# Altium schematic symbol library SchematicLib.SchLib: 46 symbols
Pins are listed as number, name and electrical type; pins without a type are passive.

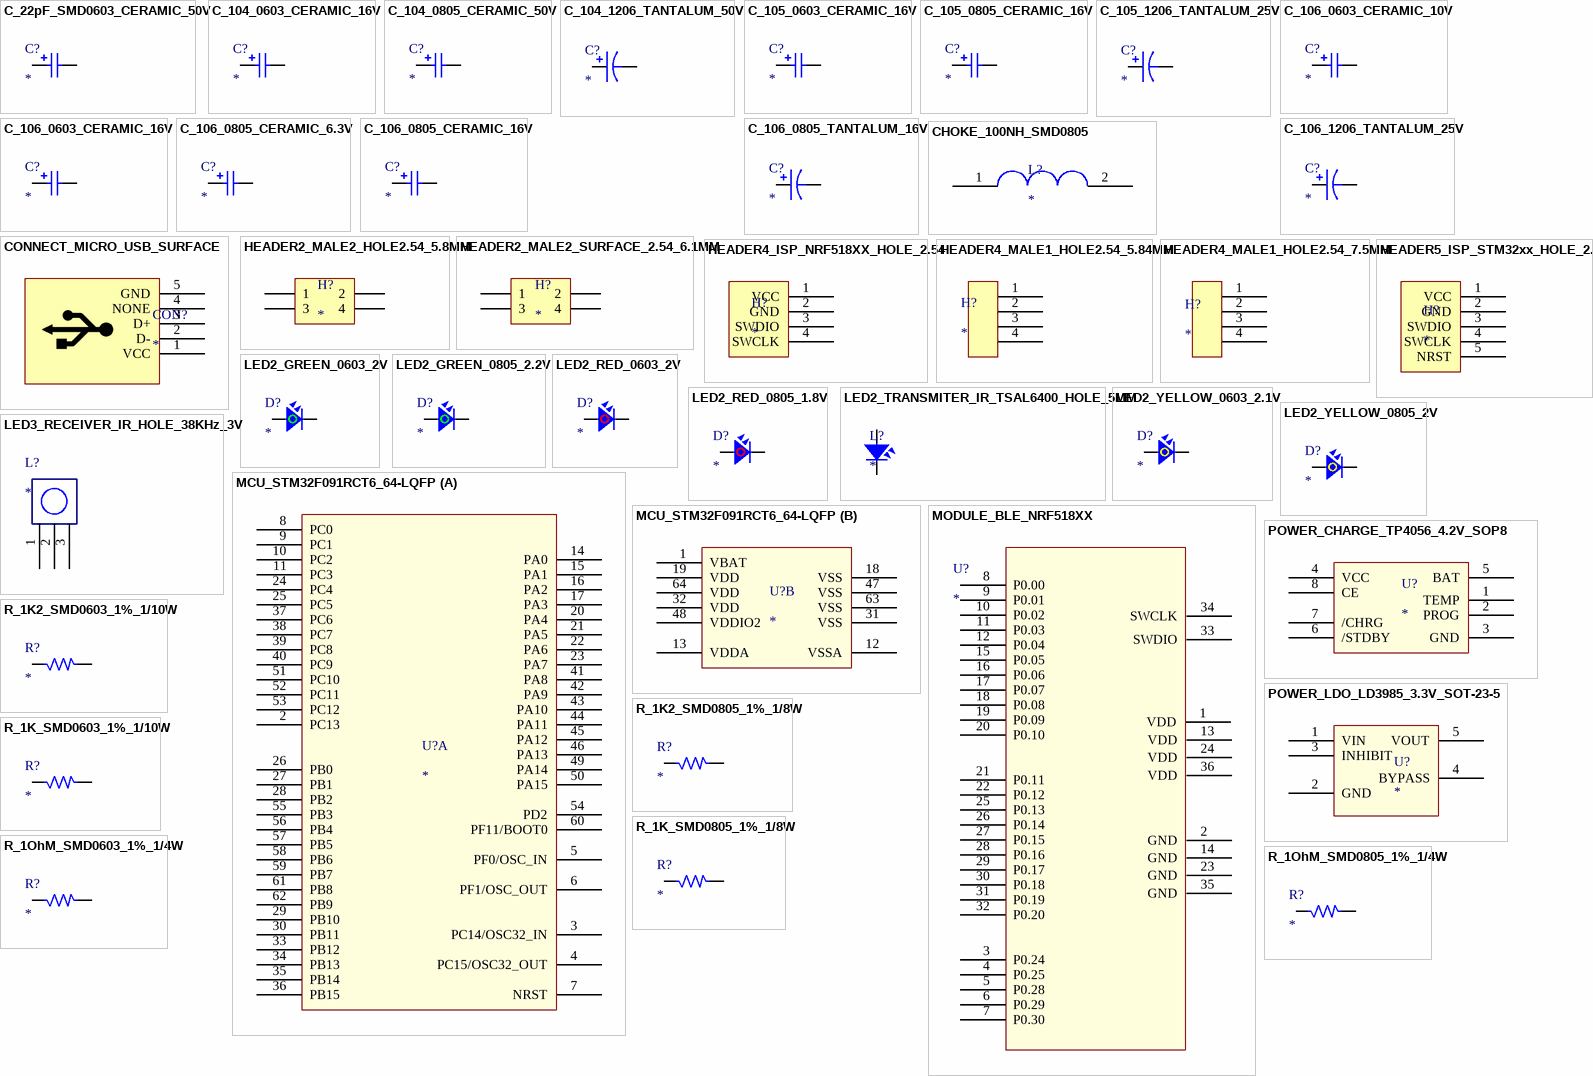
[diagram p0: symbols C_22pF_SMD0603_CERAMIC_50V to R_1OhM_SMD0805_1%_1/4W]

## C_22pF_SMD0603_CERAMIC_50V
designator C?
CAP CER 22PF 50V NP0 0603; Manufacturer: Murata Electronics North America; Manufacturer Part Number: GQM1885C1H220JB01D; Tolerance: ±5%; Temperature Coefficient: C0G, NP0
footprint CAP_SMD0603 (Compoment SMD 60x30mil)
pins: 1, 2

## C_104_0603_CERAMIC_16V
designator C?
CAP CER 0.1UF 16V X7R 0603; Manufacturer: Murata Electronics North America; Manufacturer Part Number: GRM188R71C104KA01D; Capacitance: 0.10µF; Tolerance: ±10%
footprint CAP_SMD0603 (Compoment SMD 60x30mil)
pins: 1, 2

## C_104_0805_CERAMIC_50V
designator C?
CAP CER 0.1UF 50V X7R 0805; Manufacturer: AVX Corporation; Manufacturer Part Number: 08055C104KAT2A; Capacitance: 0.10µF; Tolerance: ±10%
footprint CAP_SMD0805 (Compoment SMD 80x50mil)
pins: 1, 2

## C_104_1206_TANTALUM_50V
designator C?
CAP TANT 0.1UF 50V 10% 1206; Manufacturer: Kemet; Manufacturer Part Number: T491A104K050AT; Manufacturer Size Code: A; Capacitance: 0.1µF; ESR (Equivalent Series Resistance): 20 Ohm; Type: Molded; Lifetime @ Temp.: 2000 Hrs @ 85°C
footprint CAP_SMD1206_TANTALUM (Compoment SMD 80x50mil)
pins: 1, 2

## C_105_0603_CERAMIC_16V
designator C?
CAP CER 1UF 16V X5R 0603; Manufacturer: Murata Electronics North America; Manufacturer Part Number: GRM188R61C105KA93D; Capacitance: 1µF; Tolerance: ±10%
footprint CAP_SMD0603 (Compoment SMD 60x30mil)
pins: 1, 2

## C_105_0805_CERAMIC_16V
designator C?
CAP CER 1UF 16V X7R 0805; Manufacturer: Murata Electronics North America; Manufacturer Part Number: GRM21BR71C105KA01L; Capacitance: 1µF; Tolerance: ±10%
footprint CAP_SMD0805 (Compoment SMD 80x50mil)
pins: 1, 2

## C_105_1206_TANTALUM_25V
designator C?
CAP TANT 1UF 25V 10% 1206; Manufacturer: Kemet; Manufacturer Part Number: T491A105K025AT; Manufacturer Size Code: A; Capacitance: 1µF; ESR (Equivalent Series Resistance): 8 Ohm; Type: Molded; Lifetime @ Temp.: 2000 Hrs @ 85°C
footprint CAP_SMD1206_TANTALUM (Compoment SMD 80x50mil)
pins: 1, 2

## C_106_0603_CERAMIC_10V
designator C?
CAP CER 10UF 10V X5R 0603; Manufacturer: Murata Electronics North America; Manufacturer Part Number: GRM188R61A106KE69D; Capacitance: 10µF; Tolerance: ±10%
footprint CAP_SMD0603 (Compoment SMD 60x30mil)
pins: 1, 2

## C_106_0603_CERAMIC_16V
designator C?
CAP CER 10UF 16V X5R 0603; Manufacturer: Murata Electronics North America; Manufacturer Part Number: GRM188R61C106KAALD; Capacitance: 10µF; Tolerance: ±10%
footprint CAP_SMD0603 (Compoment SMD 60x30mil)
pins: 1, 2

## C_106_0805_CERAMIC_6.3V
designator C?
CAP CER 10UF 6.3V X5R 0805; Manufacturer: Murata Electronics North America; Manufacturer Part Number: GRM219R60J106KE19D; Capacitance: 10µF; Tolerance: ±10%
footprint CAP_SMD0805 (Compoment SMD 80x50mil)
pins: 1, 2

## C_106_0805_CERAMIC_16V
designator C?
CAP CER 10UF 16V X5R 0805; Manufacturer: Murata Electronics North America; Manufacturer Part Number: GRM21BR61C106KE15K; Capacitance: 10µF; Tolerance: ±10%
footprint CAP_SMD0805 (Compoment SMD 80x50mil)
pins: 1, 2

## C_106_0805_TANTALUM_16V
designator C?
CAP TANT 10UF 16V 10% 0805; Manufacturer: AVX Corporation; Manufacturer Part Number: TPCR106K016R1800; Manufacturer Size Code: R; Capacitance: 10µF; ESR (Equivalent Series Resistance): 1.8 Ohm; Type: Molded
footprint CAP_SMD0805 - TANTALUM (Compoment SMD 80x50mil)
pins: 1, 2

## C_106_1206_TANTALUM_25V
designator C?
CAP TANT 10UF 25V 10% 1206; Manufacturer: AVX Corporation; Manufacturer Part Number: F951E106KAAAQ2; Manufacturer Size Code: A; Capacitance: 10µF; ESR (Equivalent Series Resistance): 2 Ohm; Type: Conformal Coated
footprint CAP_SMD1206_TANTALUM (Compoment SMD 80x50mil)
pins: 1, 2

## CHOKE_100NH_SMD0805
designator L?
FIXED IND 100NH 300MA 900 MOHM; Manufacturer: Jaro Components Inc.; Manufacturer Part Number: HFI-201209-R10J; Type: Wirewound; Material - Core: Ceramic; Tolerance: ±5%; Shielding: Unshielded; DC Resistance (DCR): 900 mOhm Max; Q @ Freq: 18 @ 100MHz; Frequency - Self Resonant: 600MHz; Frequency - Test: 100MHz
pins: 1, 2

## CONNECT_MICRO_USB_SURFACE
designator CON?
CONN RCPT STD MICRO USB TYPE B; Manufacturer: Amphenol FCI; Manufacturer Part Number: 10103593-0001LF; Connector Type: USB - micro B; Number of Contacts: 5; Gender: Receptacle; Specifications: USB 2.0; Regulator Topology: Positive Fixed; Voltage - Output: 3.3V; Current - Output: 150mA; Voltage - Dropout (Typical): 0.06V @ 150mA; Number of Regulators: 1; Voltage - Input: Up to 6V; Current - Limit (Min): 300mA
footprint CON_MICRO_USB_HOLE
footprint Micro_USB
pins: 1 VCC, 2 D-, 3 D+, 4 NONE, 5 GND

## HEADER2_MALE2_HOLE2.54_5.8MM
designator H?
02+02 DIL VERT PIN HDR; Manufacturer: Harwin Inc.; Manufacturer Part Number: M20-9760246; Connector Type: Header, Unshrouded, Breakaway; Number of Positions: 4; Number of Positions Loaded: All; Pitch: 0.100" (2.54mm)
footprint HEADER2_MALE2_HOLE2.54 (HEADER, SINGLE, DISTANCE = 100mil)
pins: 1, 2, 3, 4

## HEADER2_MALE2_SURFACE_2.54_6.1MM
designator H?
CONN HEADER 4POS TIN SMD; Manufacturer: Molex, LLC; Manufacturer Part Number: 0015912040; Connector Type: Header, Unshrouded, Breakaway; Number of Positions: 4; Number of Positions Loaded: All; Pitch: 0.100" (2.54mm)
footprint HEADER2_MALE2_SURFACE2.54 (HEADER, SINGLE, DISTANCE = 100mil)
pins: 1, 2, 3, 4

## HEADER4_ISP_NRF518XX_HOLE_2.54
designator H?
CONN HEADER 4POS .100 STR TIN; Manufacturer: Amphenol FCI; Manufacturer Part Number: 68002-404HLF; Connector Type: Header, Unshrouded; Number of Positions: 4; Number of Positions Loaded: All; Pitch: 0.100" (2.54mm)
footprint HEADER4_ISP_NRF518xx_SUR1.27 (HEADER, SINGLE, DISTANCE = 100mil)
pins: 1 VCC, 2 GND, 3 SWDIO, 4 SWCLK

## HEADER4_MALE1_HOLE2.54_5.84MM
designator H?
CONN HEADER 4POS .100 STR TIN; Manufacturer: Amphenol FCI; Manufacturer Part Number: 68002-404HLF; Connector Type: Header, Unshrouded; Number of Positions: 4; Number of Positions Loaded: All; Pitch: 0.100" (2.54mm)
pins: 1, 2, 3, 4

## HEADER4_MALE1_HOLE2.54_7.5MM
designator H?
CONN HEADER VERT 4POS .100 TIN; Manufacturer: TE Connectivity AMP Connectors; Manufacturer Part Number: 640456-4; Connector Type: Header, Unshrouded; Number of Positions: 4; Number of Positions Loaded: All; Pitch: 0.100" (2.54mm)
pins: 1, 2, 3, 4

## HEADER5_ISP_STM32xx_HOLE_2.54
designator H?
CONN HEADER 5 POS 2.54; Manufacturer: Wurth Electronics Inc; Manufacturer Part Number: 61300511121; Connector Type: Header, Unshrouded; Number of Positions: 5; Number of Positions Loaded: All; Pitch: 0.100" (2.54mm)
footprint HEADER5_ISP_STM32F0xx_SUR1.27 - duplicate (HEADER, SINGLE, DISTANCE = 100mil)
pins: 1 VCC, 2 GND, 3 SWDIO, 4 SWCLK, 5 NRST

## LED2_GREEN_0603_2V
designator D?
LED GREEN CLEAR 0603 SMD; Manufacturer: Lite-On Inc.; Manufacturer Part Number: LTST-C191KGKT; Lens Color: Colorless; Millicandela Rating: 35mcd; Lens Style/Size: Rectangle with Flat Top, 1.10mm x 0.80mm; Voltage - Forward (Vf) (Typ): 2V; Current - Test: 20mA; Viewing Angle: 130°; Wavelength - Dominant: 571nm; Wavelength - Peak: 574nm
footprint LED_GREEN_SMD0603 (Compoment SMD 60x30mil)
pins: 1, 2

## LED2_GREEN_0805_2.2V
designator D?
LED GREEN DIFFUSED 0805 SMD; Manufacturer: OSRAM Opto Semiconductors Inc.; Manufacturer Part Number: LG R971-KN-1; Lens Color: White; Millicandela Rating: 26.05mcd; Lens Style/Size: Rectangle with Flat Top, 1.30mm x 1.25mm; Voltage - Forward (Vf) (Typ): 2.2V; Current - Test: 20mA; Viewing Angle: 160°; Wavelength - Dominant: 570nm; Wavelength - Peak: 572nm
footprint LED_GREEN_SMD0805 (Compoment SMD 80x50mil)
pins: 1, 2

## LED2_RED_0603_2V
designator D?
LED RED CLEAR 0603 SMD; Manufacturer: Lite-On Inc.; Manufacturer Part Number: LTST-C191KRKT; Lens Color: Colorless; Millicandela Rating: 54mcd; Lens Style/Size: Rectangle with Flat Top, 1.10mm x 0.80mm; Voltage - Forward (Vf) (Typ): 2V; Current - Test: 20mA; Viewing Angle: 130°; Wavelength - Dominant: 631nm; Wavelength - Peak: 639nm
footprint LED_RED_SMD0603 (Compoment SMD 60x30mil)
pins: 1, 2

## LED2_RED_0805_1.8V
designator D?
LED RED DIFFUSED 0805 SMD; Manufacturer: OSRAM Opto Semiconductors Inc.; Manufacturer Part Number: LH R974-LP-1; Lens Color: White; Millicandela Rating: 41mcd; Lens Style/Size: Rectangle with Flat Top, 1.30mm x 1.25mm; Voltage - Forward (Vf) (Typ): 1.8V; Current - Test: 20mA; Viewing Angle: 160°; Wavelength - Dominant: 645nm; Wavelength - Peak: 660nm
footprint LED_RED_SMD0805 (Compoment SMD 80x50mil)
pins: 1, 2

## LED2_TRANSMITER_IR_TSAL6400_HOLE_5MM
designator L?
EMITTER IR 940NM 100MA RADIAL; Manufacturer: Vishay Semiconductor Opto Division; Manufacturer Part Number: TSAL6400; Type: Infrared (IR); Radiant Intensity (Ie) Min @ If: 25mW/sr @ 100mA; Voltage - Forward (Vf) (Typ): 1.35V; Viewing Angle: 50°
footprint LED2_IR_TRANSMITOR (LED phi 5mm)
pins: 1, 2

## LED2_YELLOW_0603_2.1V
designator D?
LED YELLOW CLEAR 0603 SMD; Manufacturer: Lite-On Inc.; Manufacturer Part Number: LTST-C191KSKT; Lens Color: Colorless; Millicandela Rating: 104mcd; Lens Style/Size: Rectangle with Flat Top, 1.10mm x 0.80mm; Voltage - Forward (Vf) (Typ): 2.1V; Current - Test: 20mA; Viewing Angle: 130°; Wavelength - Dominant: 591nm; Wavelength - Peak: 588nm
footprint LED_YELLOW_SMD0603 (Compoment SMD 60x30mil)
pins: 1, 2

## LED2_YELLOW_0805_2V
designator D?
LED YELLOW DIFFUSED 0805 SMD; Manufacturer: OSRAM Opto Semiconductors Inc.; Manufacturer Part Number: LY R976-PS-36; Lens Color: White; Millicandela Rating: 162.5mcd; Lens Style/Size: Rectangle with Flat Top, 1.30mm x 1.25mm; Voltage - Forward (Vf) (Typ): 2V; Current - Test: 20mA; Viewing Angle: 160°; Wavelength - Dominant: 588nm; Wavelength - Peak: 591nm
footprint LED_GREEN_SMD0805 (Compoment SMD 80x50mil)
pins: 1, 2

## LED3_RECEIVER_IR_HOLE_38KHz_3V
designator L?
RECEIVER IR REM CTRL 3V 38KHZ; Manufacturer: Sharp Microelectronics; Manufacturer Part Number: GP1UE261XKVF; Sensing Distance: 10m; B.P.F. Center Frequency: 38.0kHz; Voltage - Supply: 2.7 V ~ 5.5 V; Current - Supply: 400µA
footprint LED3_IR_RECEIVER (HEADER, SINGLE, DISTANCE = 100mil)
pins: 1 OUT, 2 GND, 3 VCC

## MCU_STM32F091RCT6_64-LQFP
designator U?
IC MCU 32BIT 256KB FLASH 64LQFP; Manufacturer: STMicroelectronics; Manufacturer Part Number: STM32F091RCT6; Core Processor: ARM® Cortex®-M0; Core Size: 32-Bit; Speed: 48MHz; Connectivity: CAN, I²C, IrDA, LIN, SPI, UART/USART; Peripherals: DMA, I²S, POR, PWM, WDT; Number of I/O: 52; Program Memory Size: 256KB (256K x 8); RAM Size: 32K x 8; Voltage - Supply (Vcc/Vdd): 2 V ~ 3.6 V; Data Converters: A/D 19x12b, D/A 2x12b; Oscillator Type: Internal
footprint MCU_STM32F091RCT6_LQFP64 (STM32F091RCT6 LQFP64)
part A pins: 2 PC13, 3 PC14/OSC32_IN, 4 PC15/OSC32_OUT, 5 PF0/OSC_IN, 6 PF1/OSC_OUT, 7 NRST, 8 PC0, 9 PC1, 10 PC2, 11 PC3, 14 PA0, 15 PA1, 16 PA2, 17 PA3, 20 PA4, 21 PA5, 22 PA6, 23 PA7, 24 PC4, 25 PC5, 26 PB0, 27 PB1, 28 PB2, 29 PB10, 30 PB11, 33 PB12, 34 PB13, 35 PB14, 36 PB15, 37 PC6, 38 PC7, 39 PC8, 40 PC9, 41 PA8, 42 PA9, 43 PA10, 44 PA11, 45 PA12, 46 PA13, 49 PA14, 50 PA15, 51 PC10, 52 PC11, 53 PC12, 54 PD2, 55 PB3, 56 PB4, 57 PB5, 58 PB6, 59 PB7, 60 PF11/BOOT0, 61 PB8, 62 PB9
part B pins: 1 VBAT, 12 VSSA, 13 VDDA, 18 VSS, 19 VDD, 31 VSS, 32 VDD, 47 VSS, 48 VDDIO2, 63 VSS, 64 VDD

## MODULE_BLE_NRF518XX
designator U?
footprint MODULE_NRF518xx (MODULE BLE NRF51822 Madeby TUAN ANH)
pins: 1 VDD, 2 GND, 3 P0.24, 4 P0.25, 5 P0.28, 6 P0.29, 7 P0.30, 8 P0.00, 9 P0.01, 10 P0.02, 11 P0.03, 12 P0.04, 13 VDD, 14 GND, 15 P0.05, 16 P0.06, 17 P0.07, 18 P0.08, 19 P0.09, 20 P0.10, 21 P0.11, 22 P0.12, 23 GND, 24 VDD, 25 P0.13, 26 P0.14, 27 P0.15, 28 P0.16, 29 P0.17, 30 P0.18, 31 P0.19, 32 P0.20, 33 SWDIO, 34 SWCLK, 35 GND, 36 VDD

## POWER_CHARGE_TP4056_4.2V_SOP8
designator U?
IC CHARGR BATTERY L-ION  SOP8; Manufacturer: NanJing; Manufacturer Part Number: TP4056; Battery Chemistry: Lithium-Ion; Number of Cells: 1; Current - Charging: Constant - Programmable; Programmable Features: Timer; Fault Protection: Over Current, Over Temperature; Charge Current - Max: 700mA; Battery Pack Voltage: 4.2V; Voltage - Supply (Max): 8V; Supply: TAOBAO
footprint POWER__CHARGE_TP4056 (SOP, 8-Leads, Body 4.90x3.90mm, Pitch 1.27mm, IPC Medium Density)
pins: 1 TEMP, 2 PROG, 3 GND, 4 VCC, 5 BAT, 6 /STDBY, 7 /CHRG, 8 CE

## POWER_LDO_LD3985_3.3V_SOT-23-5
designator U?
IC REG LDO 3.3V 0.15A SOT23-5; Manufacturer: STMicroelectronics; Manufacturer Part Number: LD3985M33R; Regulator Topology: Positive Fixed; Current - Output: 150mA; Voltage - Dropout (Typical): 0.06V @ 150mA; Number of Regulators: 1; Voltage - Input: Up to 6V; Current - Limit (Min): 300mA
footprint POWER_LDO_LDR3985-3.3 (SOT23, 5-Leads, Body 2.90x2.80mm, Pitch 0.95mm, IPC Medium Density)
pins: 1 VIN, 2 GND, 3 INHIBIT, 4 BYPASS, 5 VOUT

## R_1K2_SMD0603_1%_1/10W
designator R?
RES SMD 1.2K OHM 1% 1/10W 0603; Manufacturer: Yageo; Manufacturer Part Number: RC0603FR-071K2L; Power (Watts): 0.1W, 1/10W; Temperature Coefficient: ±100ppm/°C
footprint RES_SMD0603 (Compoment SMD 60x30mil)
pins: 1, 2

## R_1K2_SMD0805_1%_1/8W
designator R?
RES SMD 1.2K OHM 1% 1/8W 0805; Manufacturer: Yageo; Manufacturer Part Number: RC0805FR-071K2L; Power (Watts): 0.125W, 1/8W; Temperature Coefficient: ±100ppm/°C
footprint RES_SMD0805 (Compoment SMD 80x50mil)
pins: 1, 2

## R_1K_SMD0603_1%_1/10W
designator R?
RES SMD 1K OHM 1% 1/10W 0603; Manufacturer: Yageo; Manufacturer Part Number: RC0603FR-071KL; Power (Watts): 0.1W, 1/10W; Temperature Coefficient: ±100ppm/°C
footprint RES_SMD0603 (Compoment SMD 60x30mil)
pins: 1, 2

## R_1K_SMD0805_1%_1/8W
designator R?
RES SMD 1K OHM 1% 1/8W 0805; Manufacturer: Yageo; Manufacturer Part Number: RC0805FR-071KL; Power (Watts): 0.125W, 1/8W; Temperature Coefficient: ±100ppm/°C
footprint RES_SMD0805 (Compoment SMD 80x50mil)
pins: 1, 2

## R_1OhM_SMD0603_1%_1/4W
designator R?
RES SMD 1 OHM 1% 1/4W 0603; Manufacturer: Panasonic Electronic Components; Manufacturer Part Number: ERJ-3BQF1R0V; Resistance (Ohms): 1; Power (Watts): 0.25W, 1/4W; Temperature Coefficient: ±200ppm/°C
footprint RES_SMD0603 (Compoment SMD 60x30mil)
pins: 1, 2

## R_1OhM_SMD0805_1%_1/4W
designator R?
RES SMD 1 OHM 1% 1/4W 0805; Manufacturer: Stackpole Electronics Inc.; Manufacturer Part Number: RNCP0805FTD1R00; Resistance (Ohms): 1; Power (Watts): 0.25W, 1/4W; Temperature Coefficient: ±100ppm/°C
footprint RES_SMD0805 (Compoment SMD 80x50mil)
pins: 1, 2

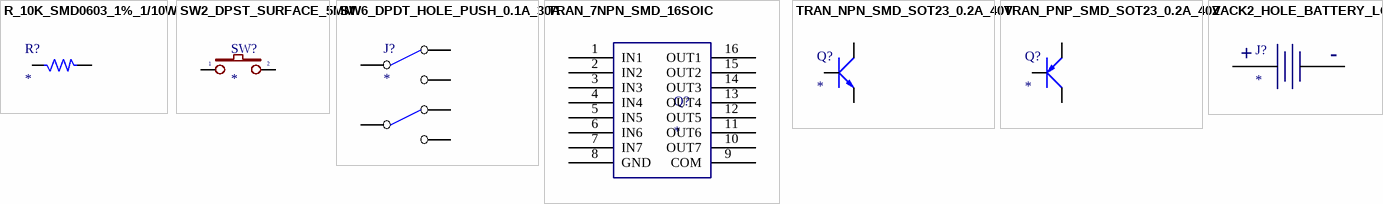
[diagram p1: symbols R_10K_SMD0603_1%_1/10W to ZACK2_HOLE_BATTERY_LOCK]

## R_10K_SMD0603_1%_1/10W
designator R?
RES SMD 10K OHM 1% 1/10W 0603; Manufacturer: Yageo; Manufacturer Part Number: RC0603FR-0710KL; Power (Watts): 0.1W, 1/10W; Temperature Coefficient: ±100ppm/°C; Capacitance: 0.10µF; Voltage - Rated: 50V
footprint RES_SMD0603 (Compoment SMD 60x30mil)
pins: 1, 2

## SW2_DPST_SURFACE_5MM
designator SW?
SWITCH TACTILE SPST-NO 0.05A 12V; Manufacturer: Wurth Electronics Inc; Manufacturer Part Number: 434121050836; Switch Function: Off-Mom; Contact Rating @ Voltage: 0.05A @ 12VDC; Actuator Type: Rectangular Button; Actuator Height off PCB, from Pins: 5.00mm; Actuator Orientation: Top Actuated; Outline: 6.00mm x 3.50mm; Illumination: Non-Illuminated; Operating Force: 360gf; Actuator Material: Liquid Crystal Polymer (LCP); Switch Travel: 0.25mm; Mechanical Life: 50,000 Cycles
footprint SW2-SMD (Switch SMD type)
pins: 1, 2

## SW6_DPDT_HOLE_PUSH_0.1A_30A
designator J?
SWITCH PUSH DPDT 0.1A 30V; Manufacturer: Apem Inc.; Manufacturer Part Number: MHPS2266; Switch Function: On-On; Current Rating: 100mA (DC); Actuator Type: Plunger for Cap; Electrical Life: 10,000 Cycles
footprint SW6_DPDT_POWER (PUSH POWER SOURCE)
pins: 1 NC, 2 COMMON, 3 NO, 4 NO, 5 COMMON, 6 NC

## TRAN_7NPN_SMD_16SOIC
designator Q?
TRANS 7NPN DARL 50V 0.5A 16SO; Manufacturer: Texas Instruments; Manufacturer Part Number: ULN2003ADR; Transistor Type: 7 NPN Darlington; Current - Collector (Ic) (Max): 500mA; Vce Saturation (Max) @ Ib, Ic: 1.6V @ 500µA, 350mA
footprint TRAN7_ULN2003_16SOIC (Small Outline; 16 Leads; Body Width 5.6 mm; Pitch 1.27 mm)
pins: 1 IN1, 2 IN2, 3 IN3, 4 IN4, 5 IN5, 6 IN6, 7 IN7, 8 GND, 9 COM, 10 OUT7, 11 OUT6, 12 OUT5, 13 OUT4, 14 OUT3, 15 OUT2, 16 OUT1

## TRAN_NPN_SMD_SOT23_0.2A_40V
designator Q?
TRANS NPN 40V 0.2A SOT23; Manufacturer: ON Semiconductor; Manufacturer Part Number: MMBT3904LT1G; Current - Collector (Ic) (Max): 200mA; Vce Saturation (Max) @ Ib, Ic: 300mV @ 5mA, 50mA; DC Current Gain (hFE) (Min) @ Ic, Vce: 100 @ 10mA, 1V; Power - Max: 300mW; Frequency - Transition: 300MHz
footprint TRAN-NPN-SMD (SOT-23; 3 Leads; Body 3.0 x 2.5 mm, inc. leads (LxW max))
pins: 1 B, 2 E, 3 C

## TRAN_PNP_SMD_SOT23_0.2A_40V
designator Q?
TRANS PNP 40V 0.2A SOT23; Manufacturer: ON Semiconductor; Manufacturer Part Number: MMBT3906LT1G; Current - Collector (Ic) (Max): 200mA; Vce Saturation (Max) @ Ib, Ic: 400mV @ 5mA, 50mA; DC Current Gain (hFE) (Min) @ Ic, Vce: 100 @ 10mA, 1V; Power - Max: 300mW; Frequency - Transition: 250MHz
footprint TRAN-PNP-SMD (SOT-23; 3 Leads; Body 3.0 x 2.5 mm, inc. leads (LxW max))
pins: 1 E, 2 C, 3 B

## ZACK2_HOLE_BATTERY_LOCK
designator J?
CONN HEADER VERT 2POS .100 TIN; Manufacturer: TE Connectivity AMP Connectors; Manufacturer Part Number: 640456-2; Connector Type: Header, Unshrouded; Number of Positions: 2; Number of Positions Loaded: All; Pitch: 0.100" (2.54mm)
footprint ZACK_BAT (HEADER, SINGLE, DISTANCE = 100mil)
pins: 1 +, 2 -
